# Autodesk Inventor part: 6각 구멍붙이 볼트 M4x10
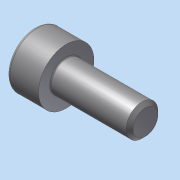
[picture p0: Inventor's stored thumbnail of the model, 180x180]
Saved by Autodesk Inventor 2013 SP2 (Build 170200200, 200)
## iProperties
Created: 2026-01
Part Number: 6각 구멍붙이 볼트 M4x10
Material: Generic
Document SubType Name: Modeling
Designer: a
Density: 1 g/cm^3
Author: a
변환 표준: STEP AP214IS
전처리기: Build: 200, Release: 2013 SP2 Update 6 - Date: Thu 07/17/2014
전송 단위: 밀리미터
불확실성: 0.01
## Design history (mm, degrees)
node "6각 구멍붙이 볼트 M4x101"
body "Solid1"
node "기준1"
